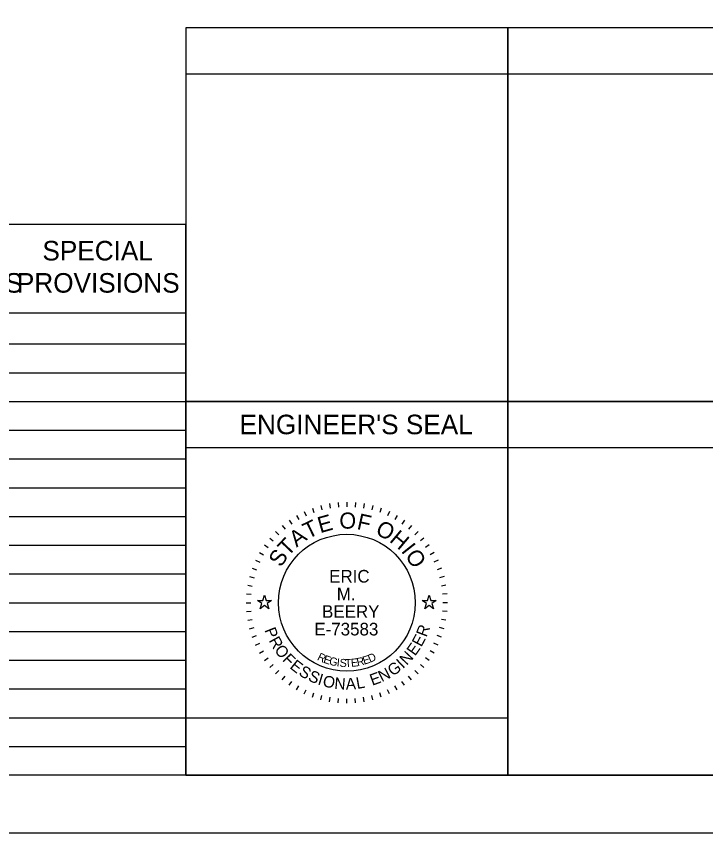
# Model space of a CAD drawing. Extents: x 0 to 34, y 0 to 22.
# Drawn here: x 22.13 to 28.12, y 0 to 7.1 of the extents above; entities that cross this region are included whole.
import ezdxf

# ---------------------------------------------------------------- set-up
doc = ezdxf.new("R2010")
doc.units = 0
for name, color, linetype in [('SH_Border', 7, 'Continuous'), ('SH_Cut_Line', 7, 'Continuous'), ('SH_Data', 7, 'Continuous'), ('SH_Seal', 7, 'Continuous'), ('SH_Text', 7, 'Continuous')]:
    doc.layers.add(name, color=color, linetype=linetype)

msp = doc.modelspace()

# ---------------------------------------------------------------- linework, layer by layer
at = {"layer": 'SH_Border'}
msp.add_lwpolyline([(1.5, 21.5), (33.5, 21.5), (33.5, 0.5), (1.5, 0.5)], close=True, dxfattribs=at)
at = {"layer": 'SH_Cut_Line'}
msp.add_lwpolyline([(0, 0), (34, 0), (34, 22), (0, 22)], close=True, dxfattribs=at)
at = {"layer": 'SH_Data'}
for p, q in [((23.6, 6.6), (26.4, 6.6)), ((26.4, 6.6), (29.2, 6.6)), ((10.15, 5.2917), (23.6, 5.2917)), ((23.6, 0.5), (23.6, 5.2917)), ((10.15, 4.5209), (23.6, 4.5209)), ((10.15, 4.25), (23.6, 4.25)), ((10.15, 4), (23.6, 4)), ((10.15, 3.75), (23.6, 3.75)), ((23.6, 0.5), (23.6, 3.75)), ((23.6, 3.75), (26.4, 3.75)), ((26.4, 3.75), (26.4, 0.5)), ((10.15, 3.5), (23.6, 3.5)), ((23.6, 3.35), (26.4, 3.35)), ((23.6, 3.35), (26.4, 3.35)), ((26.4, 3.35), (29.2, 3.35)), ((10.15, 3.25), (23.6, 3.25)), ((10.15, 3), (23.6, 3)), ((10.15, 2.75), (23.6, 2.75)), ((10.15, 2.5), (23.6, 2.5)), ((10.15, 2.25), (23.6, 2.25)), ((10.15, 2), (23.6, 2)), ((10.15, 1.75), (23.6, 1.75)), ((10.15, 1.5), (23.6, 1.5)), ((10.15, 1.25), (23.6, 1.25)), ((10.15, 1), (23.6, 1)), ((10.15, 0.75), (23.6, 0.75)), ((23.6, 0.5), (26.4, 0.5))]:
    msp.add_line(p, q, dxfattribs=at)
for points in [[(26.4, 7), (23.6, 7), (23.6, 3.75), (26.4, 3.75)], [(29.2, 7), (26.4, 7), (26.4, 3.75), (29.2, 3.75)], [(26.4, 3.75), (23.6, 3.75), (23.6, 0.5), (26.4, 0.5)], [(29.2, 3.75), (26.4, 3.75), (26.4, 0.5), (29.2, 0.5)], [(23.6, 0.5), (23.6, 1), (26.4, 1), (26.4, 0.5)]]:
    msp.add_lwpolyline(points, close=True, dxfattribs=at)
at = {"layer": 'SH_Seal'}
for p, q in [((24.7735, 2.8452), (24.7839, 2.8065)), ((24.8481, 2.8617), (24.855, 2.8223)), ((24.9237, 2.8717), (24.9272, 2.8318)), ((25, 2.875), (25, 2.835)), ((25.0763, 2.8717), (25.0728, 2.8318)), ((25.1519, 2.8617), (25.145, 2.8223)), ((25.2265, 2.8452), (25.2161, 2.8065)), ((24.6302, 2.793), (24.6471, 2.7568)), ((24.7007, 2.8222), (24.7144, 2.7846)), ((25.2993, 2.8222), (25.2856, 2.7846)), ((25.3698, 2.793), (25.3529, 2.7568)), ((24.4981, 2.7168), (24.5211, 2.684)), ((24.5625, 2.7578), (24.5825, 2.7231)), ((25.4375, 2.7578), (25.4175, 2.7231)), ((25.5019, 2.7168), (25.4789, 2.684)), ((24.4376, 2.6703), (24.4633, 2.6396)), ((25.5624, 2.6703), (25.5367, 2.6396)), ((24.3297, 2.5624), (24.3604, 2.5367)), ((24.3813, 2.6187), (24.4096, 2.5904)), ((25.6187, 2.6187), (25.5904, 2.5904)), ((25.6703, 2.5624), (25.6396, 2.5367)), ((24.2832, 2.5019), (24.316, 2.4789)), ((25.7168, 2.5019), (25.684, 2.4789)), ((24.2422, 2.4375), (24.2769, 2.4175)), ((25.7578, 2.4375), (25.7231, 2.4175)), ((24.207, 2.3698), (24.2432, 2.3529)), ((25.793, 2.3698), (25.7568, 2.3529)), ((24.1778, 2.2993), (24.2154, 2.2856)), ((25.8222, 2.2993), (25.7846, 2.2856)), ((24.1548, 2.2265), (24.1935, 2.2161)), ((25.8452, 2.2265), (25.8065, 2.2161)), ((24.1383, 2.1519), (24.1777, 2.145)), ((25.8617, 2.1519), (25.8223, 2.145)), ((24.1283, 2.0763), (24.1682, 2.0728)), ((25.8717, 2.0763), (25.8318, 2.0728)), ((24.125, 2), (24.165, 2)), ((25.875, 2), (25.835, 2)), ((24.1283, 1.9237), (24.1682, 1.9272)), ((25.8717, 1.9237), (25.8318, 1.9272)), ((24.1383, 1.8481), (24.1777, 1.855)), ((25.8617, 1.8481), (25.8223, 1.855)), ((24.1548, 1.7735), (24.1935, 1.7839)), ((25.8452, 1.7735), (25.8065, 1.7839)), ((24.1778, 1.7007), (24.2154, 1.7144)), ((25.8222, 1.7007), (25.7846, 1.7144)), ((24.207, 1.6302), (24.2432, 1.6471)), ((25.793, 1.6302), (25.7568, 1.6471)), ((24.2422, 1.5625), (24.2769, 1.5825)), ((25.7578, 1.5625), (25.7231, 1.5825)), ((24.2832, 1.4981), (24.316, 1.5211)), ((25.7168, 1.4981), (25.684, 1.5211)), ((24.3297, 1.4376), (24.3604, 1.4633)), ((25.6703, 1.4376), (25.6396, 1.4633)), ((24.3813, 1.3813), (24.4096, 1.4096)), ((24.4376, 1.3297), (24.4633, 1.3604)), ((25.5624, 1.3297), (25.5367, 1.3604)), ((25.6187, 1.3813), (25.5904, 1.4096)), ((24.4981, 1.2832), (24.5211, 1.316)), ((25.5019, 1.2832), (25.4789, 1.316)), ((24.5625, 1.2422), (24.5825, 1.2769)), ((24.6302, 1.207), (24.6471, 1.2432)), ((24.7007, 1.1778), (24.7144, 1.2154)), ((25.2993, 1.1778), (25.2856, 1.2154)), ((25.3698, 1.207), (25.3529, 1.2432)), ((25.4375, 1.2422), (25.4175, 1.2769)), ((24.7735, 1.1548), (24.7839, 1.1935)), ((24.8481, 1.1383), (24.855, 1.1777)), ((24.9237, 1.1283), (24.9272, 1.1682)), ((25, 1.125), (25, 1.165)), ((25.0763, 1.1283), (25.0728, 1.1682)), ((25.1519, 1.1383), (25.145, 1.1777)), ((25.2265, 1.1548), (25.2161, 1.1935))]:
    msp.add_line(p, q, dxfattribs=at)
for points in [[(24.2236, 2.02), (24.2705, 2.02), (24.285, 2.0645), (24.2995, 2.02), (24.3464, 2.02), (24.3085, 1.9924), (24.323, 1.9478), (24.285, 1.9754), (24.247, 1.9478), (24.2615, 1.9924)], [(25.6536, 2.02), (25.7005, 2.02), (25.715, 2.0645), (25.7295, 2.02), (25.7764, 2.02), (25.7385, 1.9924), (25.753, 1.9478), (25.715, 1.9754), (25.677, 1.9478), (25.6915, 1.9924)]]:
    msp.add_lwpolyline(points, close=True, dxfattribs=at)
msp.add_circle((25, 2), 0.595, dxfattribs=at)

# ---------------------------------------------------------------- texts
at = {"layer": 'SH_Data'}
msp.add_text("ENGINEER'S SEAL", height=0.17, dxfattribs=at).set_placement((24.0676, 3.465))
at = {"layer": 'SH_Seal'}
for s, height, rotation, p in [('E', 0.14, 15.75706, (24.7684, 2.6038)), ('O', 0.14, 359.78119, (24.9347, 2.6443)), ('F', 0.14, 347.43619, (25.0811, 2.6417)), ('T', 0.14, 25.71674, (24.6616, 2.5518)), ('O', 0.14, 332.25863, (25.2398, 2.6015)), ('A', 0.14, 36.47472, (24.5634, 2.4781)), ('H', 0.14, 319.91363, (25.3632, 2.5361)), ('T', 0.14, 46.4344, (24.4883, 2.3964)), ('I', 0.14, 308.36695, (25.4665, 2.4483)), ('S', 0.14, 57.19238, (24.4281, 2.3014)), ('O', 0.14, 303.14906, (25.5021, 2.4089)), ('P', 0.1, 291.49398, (24.2823, 1.7621)), ('R', 0.1, 69.23216, (25.6919, 1.6954)), ('R', 0.1, 298.73106, (24.319, 1.6717)), ('E', 0.1, 61.99508, (25.6476, 1.6098)), ('E', 0.1, 54.75801, (25.5933, 1.5314)), ('O', 0.1, 306.46664, (24.3655, 1.5883)), ('R', 0.07, 334.48695, (24.7375, 1.5051)), ('N', 0.1, 47.02243, (25.5202, 1.4508)), ('F', 0.1, 314.7068, (24.4343, 1.4983)), ('E', 0.1, 321.43929, (24.4978, 1.4348)), ('E', 0.07, 341.03996, (24.7906, 1.4801)), ('G', 0.07, 347.47515, (24.8414, 1.4618)), ('I', 0.07, 353.78581, (24.9091, 1.4468)), ('S', 0.07, 356.89262, (24.9358, 1.4429)), ('T', 0.07, 3.00609, (24.9857, 1.4387)), ('E', 0.07, 6.01169, (25.0389, 1.4412)), ('R', 0.07, 11.91844, (25.0925, 1.4474)), ('E', 0.07, 17.68363, (25.1498, 1.4602)), ('D', 0.07, 23.30524, (25.201, 1.477)), ('I', 0.1, 43.28703, (25.4868, 1.4214)), ('S', 0.1, 328.67637, (24.5743, 1.3752)), ('N', 0.1, 27.31129, (25.3045, 1.3075)), ('G', 0.1, 35.04687, (25.3981, 1.357)), ('S', 0.1, 335.91345, (24.6564, 1.3266)), ('I', 0.1, 343.15053, (24.7406, 1.2897)), ('O', 0.1, 346.88592, (24.7839, 1.2751)), ('N', 0.1, 355.12608, (24.8888, 1.2517)), ('L', 0.1, 10.09874, (25.0894, 1.249)), ('E', 0.1, 20.07421, (25.2212, 1.277)), ('A', 0.1, 2.86166, (24.9923, 1.2437))]:
    msp.add_text(s, height=height, rotation=rotation, dxfattribs=at).set_placement(p)
for s, p in [('ERIC', (24.8465, 2.1749)), ('M.', (24.9126, 2.0216)), ('BEERY', (24.7848, 1.8684)), ('E-73583', (24.7177, 1.7151))]:
    msp.add_text(s, height=0.11, dxfattribs=at).set_placement(p)
at = {"layer": 'SH_Text'}
for s, p in [('SPECIAL', (22.3542, 4.9763)), ('SPECIFICATIONS', (20.2871, 4.6963)), ('PROVISIONS', (22.1323, 4.6963))]:
    msp.add_text(s, height=0.17, dxfattribs=at).set_placement(p)

doc.saveas('drawing.dxf')
